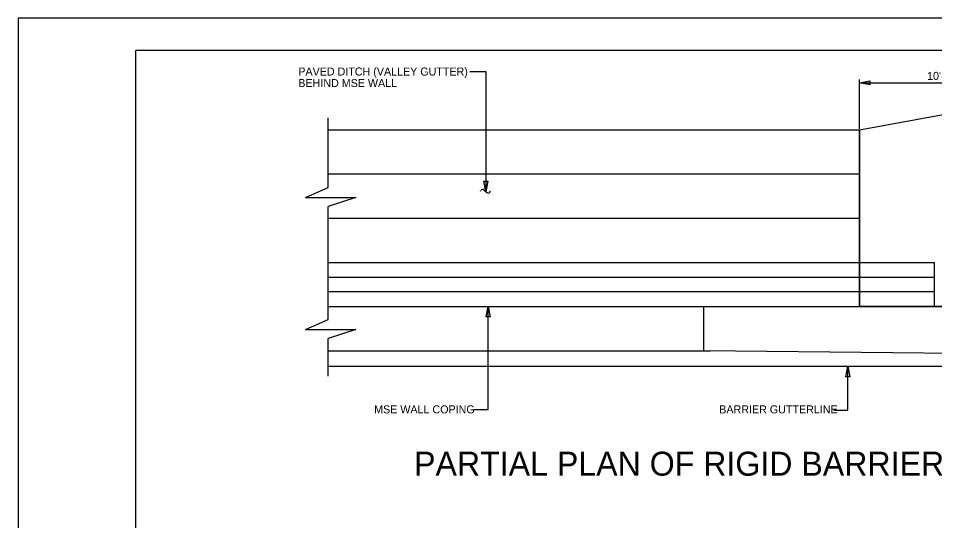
# Model space of a CAD drawing. Extents: x 96 to 240, y 601 to 689.
# Drawn here: x 95.8 to 153.1, y 657.6 to 689 of the extents above; entities that cross this region are included whole.
import ezdxf

# ---------------------------------------------------------------- set-up
doc = ezdxf.new("R2010")
doc.units = 0
for name, color, linetype in [('BR_AUTO DIMENSION', 7, 'Continuous'), ('BR_BORDER LINES', 7, 'Continuous'), ('BR_CONCRETE', 7, 'Continuous'), ('BR_TEXT', 7, 'Continuous'), ('Level 31', 7, 'Continuous')]:
    doc.layers.add(name, color=color, linetype=linetype)

msp = doc.modelspace()

# ---------------------------------------------------------------- linework, layer by layer
at = {"layer": 'BR_AUTO DIMENSION'}
for p, q in [((124.033, 685.686), (125.041, 685.686)), ((125.041, 685.686), (125.041, 678.176)), ((148.363, 682.108), (148.363, 685.177)), ((148.363, 684.981), (159.066, 684.981)), ((115.181, 678.434), (115.181, 682.797)), ((113.78, 677.819), (115.181, 678.434)), ((113.78, 677.819), (116.921, 677.819)), ((116.921, 677.819), (115.181, 677.254)), ((115.181, 670.181), (115.181, 677.254)), ((125.185, 664.568), (125.185, 670.994)), ((113.78, 669.566), (115.181, 670.181)), ((113.78, 669.566), (116.921, 669.566)), ((116.921, 669.566), (115.181, 669.001)), ((115.181, 666.643), (115.181, 669.001)), ((147.635, 664.515), (147.635, 667.262)), ((124.277, 664.568), (125.185, 664.568)), ((146.762, 664.515), (147.635, 664.515))]:
    msp.add_line(p, q, dxfattribs=at)
for points in [[(149.013, 684.856), (148.363, 684.981), (149.013, 685.106)], [(125.166, 678.826), (125.041, 678.176), (124.916, 678.826)], [(125.06, 670.344), (125.185, 670.994), (125.31, 670.344)], [(147.51, 666.612), (147.635, 667.262), (147.76, 666.612)]]:
    msp.add_lwpolyline(points, close=True, dxfattribs=at)
at = {"layer": 'BR_BORDER LINES'}
for p in [(237.837, 687.003), (103.173, 603.003)]:
    msp.add_line(p, (103.173, 687.003), dxfattribs=at)
at = {"layer": 'BR_CONCRETE'}
for p, q in [((115.181, 682.045), (148.363, 682.045)), ((148.363, 682.045), (148.363, 673.757)), ((148.363, 682.045), (148.363, 670.994)), ((115.181, 679.283), (148.363, 679.283)), ((115.181, 676.52), (148.363, 676.52)), ((115.181, 673.757), (148.363, 673.757)), ((148.363, 673.757), (153.066, 673.757)), ((153.066, 670.994), (153.066, 673.757)), ((115.181, 672.836), (153.066, 672.836)), ((153.066, 671.915), (115.181, 671.915)), ((115.181, 670.994), (161.649, 670.994)), ((115.181, 670.994), (148.363, 670.994)), ((138.644, 668.232), (138.644, 670.994)), ((115.181, 668.232), (138.644, 668.232)), ((161.649, 667.994), (138.644, 668.232)), ((115.181, 667.262), (158.46, 667.262))]:
    msp.add_line(p, q, dxfattribs=at)
at = {"layer": 'BR_TEXT'}
for p, q in [((124.704, 678.204), (124.734, 678.25)), ((124.938, 678.271), (125.101, 678.121)), ((125.279, 678.143), (125.322, 678.204))]:
    msp.add_line(p, q, dxfattribs=at)
msp.add_lwpolyline([(159.066, 670.994), (148.363, 670.994), (148.363, 682.045), (159.066, 683.99)], close=True, dxfattribs=at)
for centre, radius, start, end in [((124.844, 678.189), 0.125, 41.007, 150.8059), ((125.181, 678.196), 0.111, 223.4519, 331.7375)]:
    msp.add_arc(centre, radius, start, end, dxfattribs=at)
at = {"layer": 'Level 31'}
msp.add_line((138.644, 668.232), (139.072, 668.232), dxfattribs=at)
msp.add_lwpolyline([(95.84, 601.004), (239.84, 601.004), (239.84, 689.004), (95.84, 689.004)], close=True, dxfattribs=at)

# ---------------------------------------------------------------- texts
at = {"layer": 'BR_AUTO DIMENSION'}
for s, p in [('PAVED DITCH (VALLEY GUTTER)', (113.326, 685.43)), ('10\'-0"', (152.593, 685.16)), ('BEHIND MSE WALL', (113.326, 684.71)), ('MSE WALL COPING', (118.061, 664.323)), ('BARRIER GUTTERLINE', (139.615, 664.323))]:
    msp.add_text(s, height=0.5, dxfattribs=at).set_placement(p)
at = {"layer": 'BR_TEXT'}
msp.add_text('PARTIAL PLAN OF RIGID BARRIER - MSE WALL', height=1.5, dxfattribs=at).set_placement((120.556, 660.429))

doc.saveas('drawing.dxf')
